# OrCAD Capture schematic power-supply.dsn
size A; title: Linear Regulated Power Supply
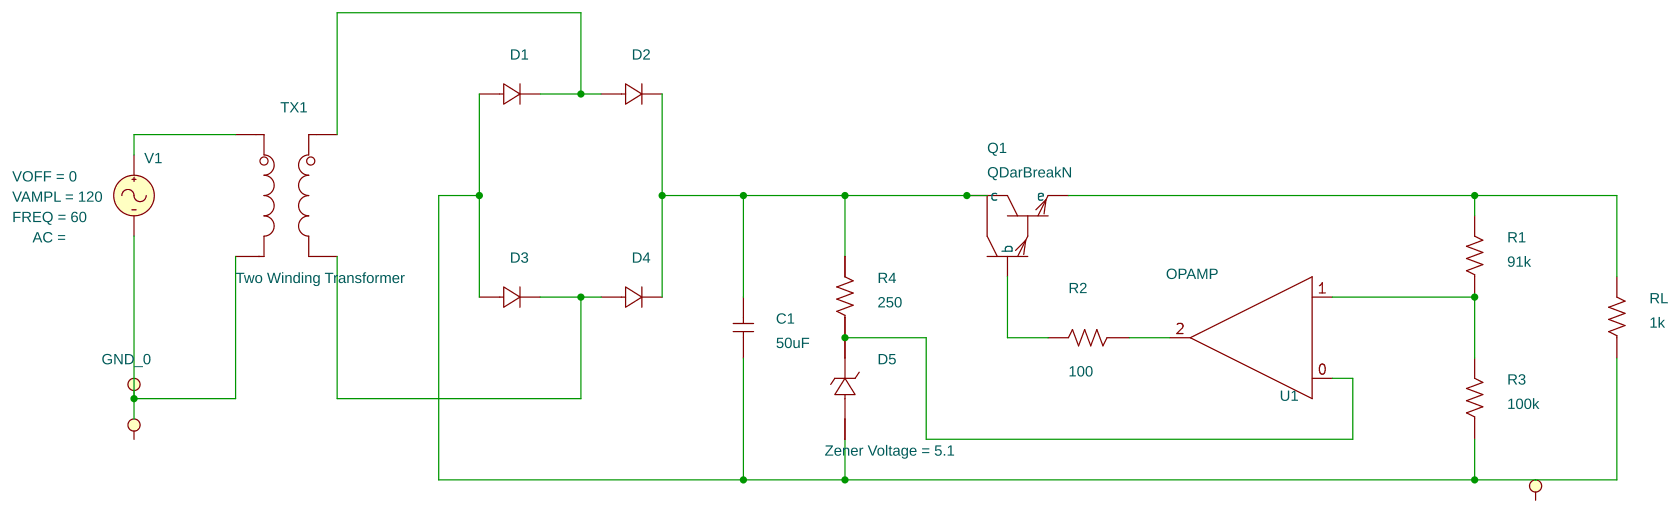
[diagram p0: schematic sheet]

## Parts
C1  50uF  [cap196]
D1  Dbreak
D2  Dbreak
D3  Dbreak
D4  Dbreak
D5  ZENER
Q1  QDarBreakN
R1  91k  [AXRC05]
R2  100  [AXRC05]
R3  100k  [AXRC05]
R4  250  [AXRC05]
RL  1k  [AXRC05]
TX1  Two Winding Transformer
U1  OPAMP
V1  VSIN

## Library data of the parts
C1 = C
D1-D4 = Dbreak
D5 = zener: AppProp: mN=MyZenerPart1,zV=5.1,TCBV=1.7,TCU=radio0; PartNumber: MyZenerPart1; TCBV: 1.7; VZT: 5.1; Zener Voltage: 5.1
Q1 = QDarBreakN
R1-R4 RL = R
TX1 = ST: AppProp: modelname=ST_Model3,LP1=1m,RP1=10m,Rs1=10m,N=0.1,LI=100n
U1 = OPAMP
V1 = VSIN: FREQ: 60; VAMPL: 120; VOFF: 0

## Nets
0: C1.1 D1.0(1) D3.0(1) D5.1(AN) R3.1 RL.1 TX1.2 V1.2(-)
N15276: TX1.1 V1.1(+)
N19142: D1.1(2) D2.0(1) TX1.3
N19190: C1.2 D2.1(2) D4.1(2) Q1.1(c) R4.2
N19250: D3.1(2) D4.0(1) TX1.4
N21454: Q1.2(e) R1.2 RL.2
N21512: R1.1 R3.2 U1.1(-)
N21548: R2.1 U1.2(OUT)
N26548: D5.2(CAT) R4.1 U1.0(+)
N28968: Q1.0(b) R2.2
